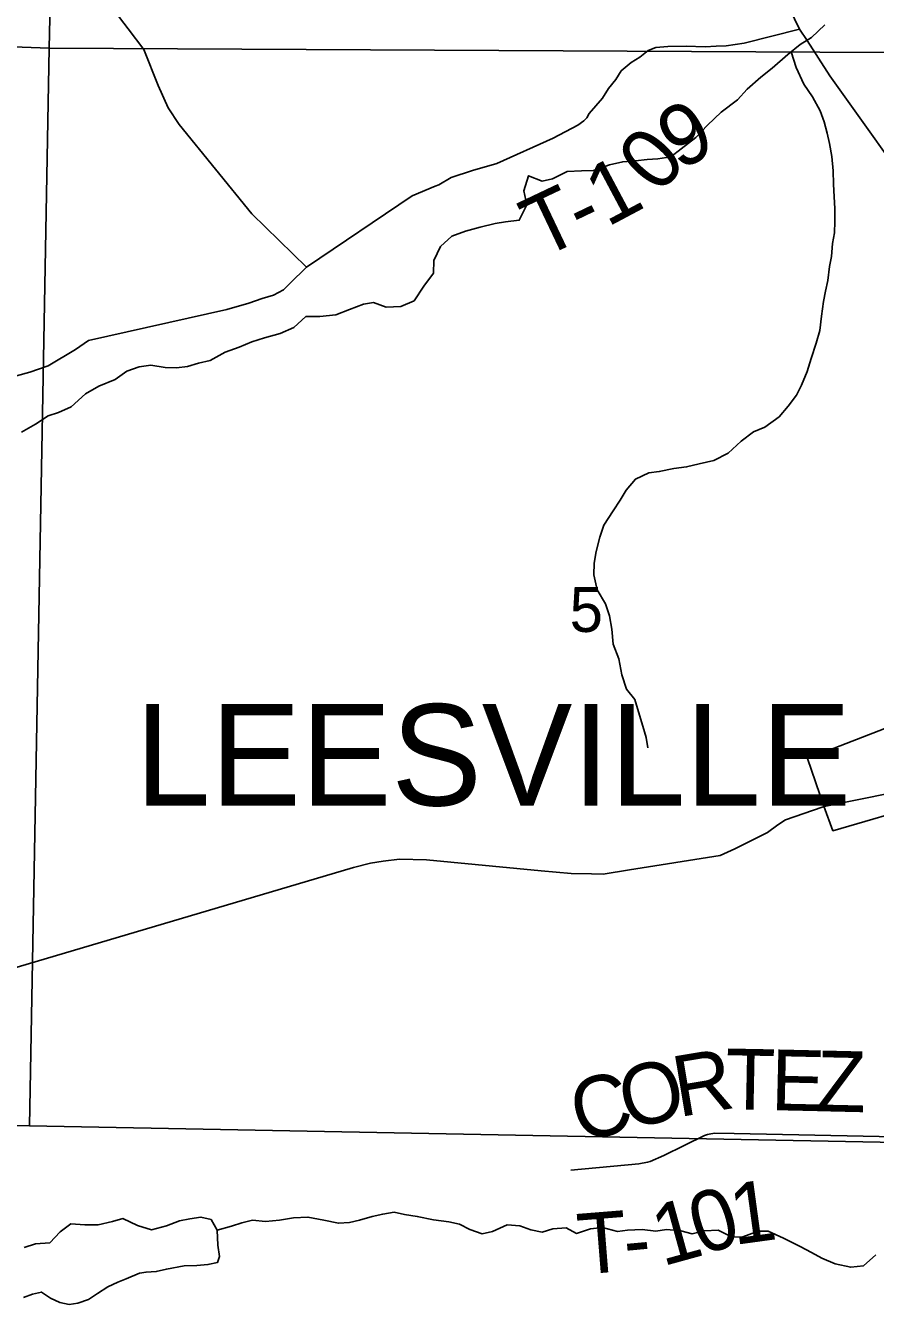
# Model space of a CAD drawing. Extents: x -1.2 to 34, y -8.5 to 22.
# Drawn here: x 4.454 to 5.247, y 18.504 to 19.699 of the extents above; entities that cross this region are included whole.
import ezdxf

# ---------------------------------------------------------------- set-up
doc = ezdxf.new("R2010")
doc.units = 0
for name, color, linetype in [('GM_X_Corporation', 7, 'Continuous'), ('GM_X_Corporation_Text', 7, 'Continuous'), ('GM_X_County_Road', 7, 'Continuous'), ('GM_X_Minor_Lake', 7, 'Continuous'), ('GM_X_Minor_River', 7, 'Continuous'), ('GM_X_Section', 7, 'Continuous'), ('GM_X_Section_Text', 7, 'Continuous'), ('GM_X_State_Route', 7, 'Continuous'), ('GM_X_Township_Road', 7, 'Continuous'), ('GM_X_Township_Road_Text', 7, 'Continuous')]:
    doc.layers.add(name, color=color, linetype=linetype)

msp = doc.modelspace()

# ---------------------------------------------------------------- linework, layer by layer
at = {"layer": 'GM_X_Corporation'}
msp.add_lwpolyline([(5.2952, 18.9721), (5.2078, 18.9465), (5.1994, 18.9696), (5.184, 19.014), (5.338, 19.0737)], dxfattribs=at)
at = {"layer": 'GM_X_County_Road'}
for points in [[(5.1977, 18.9684), (5.1996, 18.9691), (5.2629, 18.982), (5.2885, 18.9924), (5.3162, 19.0036), (5.3209, 19.0046), (5.3283, 19.0054), (5.3364, 19.0057), (5.3595, 19.0102), (5.3938, 19.0111), (5.4707, 19.007)], [(4.3866, 18.8016), (4.7601, 18.9122), (4.7759, 18.9162), (4.7876, 18.9181), (4.803, 18.9199), (4.828, 18.9193), (4.9353, 18.9092), (4.9632, 18.9067), (4.9822, 18.9062), (4.993, 18.906), (5.0177, 18.91), (5.1023, 18.9235), (5.1162, 18.9295), (5.1465, 18.945), (5.1563, 18.952), (5.1635, 18.9567), (5.1977, 18.9684)]]:
    msp.add_lwpolyline(points, dxfattribs=at)
at = {"layer": 'GM_X_Minor_Lake'}
for points in [[(4.6327, 18.5734), (4.6269, 18.5833), (4.6174, 18.5855), (4.6072, 18.5838), (4.5973, 18.5819), (4.5852, 18.5772), (4.5712, 18.5737), (4.5582, 18.5777), (4.5445, 18.5841), (4.5347, 18.5813), (4.5214, 18.5782), (4.5089, 18.5784), (4.4959, 18.5791), (4.4861, 18.5718), (4.4763, 18.5615), (4.463, 18.5606), (4.4524, 18.5571)], [(4.4517, 18.5104), (4.46, 18.5135), (4.4684, 18.5155), (4.4768, 18.5098), (4.4855, 18.5057), (4.4943, 18.5039), (4.5026, 18.5051), (4.5125, 18.5086), (4.5208, 18.514), (4.5306, 18.5202), (4.5397, 18.5248), (4.5476, 18.5279), (4.5601, 18.533), (4.5662, 18.5341), (4.5757, 18.5346), (4.5852, 18.537), (4.6019, 18.5401), (4.6136, 18.5402), (4.6239, 18.5411), (4.633, 18.5431), (4.6348, 18.5488), (4.6332, 18.5594), (4.6327, 18.5734)]]:
    msp.add_lwpolyline(points, dxfattribs=at)
at = {"layer": 'GM_X_Minor_River'}
for points in [[(5.2003, 19.6997), (5.1878, 19.6878), (5.1773, 19.6813), (5.1656, 19.6717), (5.1509, 19.6591), (5.1403, 19.6506), (5.1275, 19.6395), (5.1185, 19.6296), (5.1034, 19.6181), (5.0906, 19.6058), (5.0797, 19.5943), (5.0661, 19.5836), (5.0563, 19.5763), (5.0441, 19.5743), (5.0343, 19.5738), (5.0233, 19.5726), (5.0115, 19.5717), (4.999, 19.5686), (4.9842, 19.5635), (4.9728, 19.5631), (4.9595, 19.5626), (4.9459, 19.5556), (4.9361, 19.5536), (4.9235, 19.5585), (4.919, 19.5444), (4.9218, 19.5315), (4.9147, 19.517), (4.9018, 19.5154), (4.8923, 19.5138), (4.8783, 19.5106), (4.8647, 19.5067), (4.8518, 19.5021), (4.8413, 19.4925), (4.8349, 19.4795), (4.8346, 19.4674), (4.8256, 19.4555), (4.8166, 19.4418), (4.8042, 19.4364), (4.7905, 19.4359), (4.7787, 19.44), (4.7692, 19.4384), (4.7563, 19.4337), (4.7434, 19.4287), (4.7286, 19.427), (4.7154, 19.4269), (4.7041, 19.4166), (4.6916, 19.4111), (4.6768, 19.4072), (4.665, 19.4033), (4.6533, 19.3983), (4.6401, 19.3936), (4.6261, 19.3859), (4.6151, 19.3835), (4.6049, 19.3804), (4.5946, 19.3792), (4.584, 19.3795), (4.5707, 19.3816), (4.5597, 19.38), (4.5483, 19.3761), (4.5374, 19.3681), (4.5222, 19.3619), (4.5097, 19.3549), (4.4962, 19.3427), (4.4844, 19.3373), (4.4746, 19.3341), (4.4629, 19.3264), (4.45, 19.3191)], [(5.1689, 19.6744), (5.1733, 19.6596), (5.1806, 19.6441), (5.1887, 19.6324), (5.1957, 19.6192), (5.1995, 19.609), (5.2023, 19.5984), (5.2047, 19.5886), (5.2067, 19.5764), (5.2079, 19.5632), (5.2084, 19.5507), (5.2089, 19.5389), (5.2094, 19.5279), (5.2095, 19.5158), (5.2092, 19.5051), (5.2074, 19.4953), (5.2064, 19.4831), (5.2045, 19.4736), (5.2031, 19.4607), (5.2009, 19.4508), (5.1991, 19.4409), (5.197, 19.4272), (5.1956, 19.414), (5.1922, 19.4022), (5.1874, 19.3877), (5.1837, 19.3755), (5.1785, 19.363), (5.1737, 19.3534), (5.1658, 19.3431), (5.1575, 19.3332), (5.1443, 19.3236), (5.1337, 19.3193), (5.122, 19.3105), (5.11, 19.2994), (5.0964, 19.2924), (5.0827, 19.2893), (5.071, 19.2865), (5.0592, 19.2849), (5.0455, 19.2821), (5.0357, 19.2809), (5.0232, 19.2751), (5.0146, 19.2648), (5.0089, 19.2553), (5.0026, 19.2453), (4.9939, 19.232), (4.9899, 19.2209), (4.9866, 19.2076), (4.9848, 19.1966), (4.9845, 19.1856), (4.9876, 19.1716), (4.9953, 19.1584), (4.9992, 19.1474), (5.0012, 19.1349), (5.0025, 19.1209), (5.0079, 19.1073), (5.0107, 19.0921), (5.015, 19.0789), (5.0227, 19.0691), (5.0262, 19.0577), (5.0301, 19.0441), (5.0333, 19.0335), (5.0349, 19.024)], [(4.9362, 18.5715), (4.9256, 18.5737), (4.9153, 18.5774), (4.9035, 18.5784), (4.8899, 18.5722), (4.88, 18.5699), (4.8686, 18.5739), (4.859, 18.5788), (4.8491, 18.581), (4.8347, 18.5831), (4.8195, 18.5861), (4.8077, 18.5878), (4.7978, 18.59), (4.7872, 18.5884), (4.7773, 18.5861), (4.7656, 18.5826), (4.7561, 18.5806), (4.7458, 18.5797), (4.7322, 18.5826), (4.7173, 18.5856), (4.704, 18.5847), (4.6907, 18.5827), (4.6778, 18.5814), (4.6657, 18.5825), (4.6558, 18.5801), (4.646, 18.577), (4.6327, 18.5734), (4.6269, 18.5833), (4.6174, 18.5855), (4.6072, 18.5838), (4.5973, 18.5819), (4.5852, 18.5772), (4.5712, 18.5737), (4.5582, 18.5777), (4.5445, 18.5841), (4.5347, 18.5813), (4.5214, 18.5782), (4.5089, 18.5784), (4.4959, 18.5791), (4.4861, 18.5718), (4.4763, 18.5615), (4.463, 18.5606), (4.4524, 18.5571)], [(5.2478, 18.5502), (5.2362, 18.5399), (5.2244, 18.5386), (5.2099, 18.5419), (5.1973, 18.5472), (5.1878, 18.5524), (5.1771, 18.558), (5.1615, 18.5658), (5.1474, 18.5725), (5.1379, 18.5725), (5.1235, 18.567), (5.1136, 18.5669), (5.1007, 18.5733), (5.0877, 18.5728), (5.0764, 18.57), (5.0657, 18.5726), (5.0524, 18.574), (5.0422, 18.5724), (5.0296, 18.5738), (5.016, 18.5733), (5.0065, 18.5721), (4.9924, 18.5758), (4.9814, 18.5745), (4.9681, 18.5702), (4.9586, 18.5755), (4.9461, 18.5746), (4.9362, 18.5715)]]:
    msp.add_lwpolyline(points, dxfattribs=at)
at = {"layer": 'GM_X_Section'}
for points in [[(3.4838, 20.6845), (4.4978, 20.6761), (4.4756, 19.6778), (3.4745, 19.7148)], [(5.5138, 20.6632), (5.4939, 19.7699), (5.4956, 19.6725), (4.4756, 19.6778), (4.4978, 20.6761)], [(3.4745, 19.7148), (4.4756, 19.6778), (4.4573, 18.6708), (3.4647, 18.6909)], [(4.4756, 19.6778), (5.4956, 19.6725), (5.4804, 18.7665), (5.479, 18.6512), (4.4573, 18.6708)]]:
    msp.add_lwpolyline(points, close=True, dxfattribs=at)
at = {"layer": 'GM_X_State_Route'}
msp.add_lwpolyline([(5.1434, 19.764), (5.1765, 19.6954), (5.1836, 19.6849), (5.2048, 19.6519), (5.2942, 19.5266), (5.3768, 19.4104), (5.444, 19.3156), (5.4526, 19.3023)], dxfattribs=at)
at = {"layer": 'GM_X_Township_Road'}
for points in [[(4.716, 19.4732), (4.6649, 19.5231), (4.5971, 19.6063), (4.5868, 19.6221), (4.5775, 19.643), (4.5642, 19.6764), (4.5494, 19.6957), (4.5275, 19.725), (4.5174, 19.7356), (4.5048, 19.7459), (4.4859, 19.7592), (4.4772, 19.7681), (4.4711, 19.7762), (4.4674, 19.7811), (4.4625, 19.7853), (4.4575, 19.787), (4.4482, 19.7883)], [(5.1765, 19.6954), (5.1248, 19.6823), (5.1079, 19.68), (5.0987, 19.6795)], [(5.0987, 19.6795), (5.0884, 19.679), (5.0706, 19.6797), (5.0534, 19.6793), (5.0425, 19.6784), (5.0352, 19.6757), (5.0273, 19.6694), (5.0192, 19.6644), (5.01, 19.6565), (5.0049, 19.6486), (4.9982, 19.64), (4.9926, 19.6311), (4.9802, 19.6167), (4.9778, 19.6128), (4.9751, 19.6099), (4.9696, 19.6058), (4.9464, 19.5938), (4.8939, 19.5701), (4.8711, 19.5636), (4.8512, 19.557), (4.8398, 19.5502), (4.8361, 19.5487), (4.8149, 19.5399), (4.716, 19.4732)], [(4.716, 19.4732), (4.7006, 19.4578), (4.6946, 19.4521), (4.6853, 19.447), (4.6746, 19.4437), (4.6621, 19.4395), (4.6417, 19.4335), (4.5125, 19.4047), (4.5004, 19.3961), (4.4749, 19.381), (4.4577, 19.3749), (4.3137, 19.3354), (4.3119, 19.3347), (4.3112, 19.3343), (4.3106, 19.3335), (4.3101, 19.3325), (4.31, 19.3309), (4.3105, 19.3297), (4.3115, 19.3285), (4.3192, 19.3211), (4.3205, 19.3196)], [(4.9631, 18.6293), (5.0266, 18.6353), (5.0346, 18.6368), (5.0372, 18.6374), (5.0497, 18.643), (5.0878, 18.6619), (5.0905, 18.6627), (5.0938, 18.6634), (5.0973, 18.6639), (5.1156, 18.6635), (5.3113, 18.6596), (5.3277, 18.6599), (5.3381, 18.6605), (5.345, 18.6633), (5.3499, 18.6671), (5.3551, 18.6728), (5.3804, 18.7111), (5.3871, 18.7213), (5.3882, 18.7342), (5.3878, 18.7665)]]:
    msp.add_lwpolyline(points, dxfattribs=at)

# ---------------------------------------------------------------- texts
at = {"layer": 'GM_X_Corporation_Text'}
msp.add_text('LEESVILLE', height=0.0947, rotation=0, dxfattribs=at).set_placement((4.556, 18.9701))
at = {"layer": 'GM_X_Section_Text'}
msp.add_text('5', height=0.0419, rotation=0, dxfattribs=at).set_placement((4.9618, 19.1323))
at = {"layer": 'GM_X_Township_Road_Text'}
for s, rotation, p in [('9', 27.9034, (5.064, 19.5627)), ('0', 48.1531, (5.0448, 19.5399)), ('1', 28.0076, (4.9968, 19.5101)), ('T', 25.4083, (4.9349, 19.4805)), ('-', 25.6389, (4.9735, 19.4989)), ('R', 9.461, (5.0636, 18.6788)), ('T', 358.9093, (5.1069, 18.6863)), ('E', 358.6842, (5.1493, 18.6855)), ('Z', 358.6842, (5.1918, 18.6845)), ('O', 14.4038, (5.0164, 18.6666)), ('C', 14.4187, (4.9712, 18.655)), ('1', 7.7912, (5.1154, 18.5594)), ('0', 17.8064, (5.0846, 18.5493)), ('1', 15.4492, (5.0484, 18.5393)), ('T', 4.5711, (4.9713, 18.5317)), ('-', 5.222, (5.0143, 18.5352))]:
    msp.add_text(s, height=0.0568, rotation=rotation, dxfattribs=at).set_placement(p)

doc.saveas('drawing.dxf')
